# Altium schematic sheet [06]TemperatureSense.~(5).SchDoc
size A4; SheetNumber: 4; SheetTotal: 4
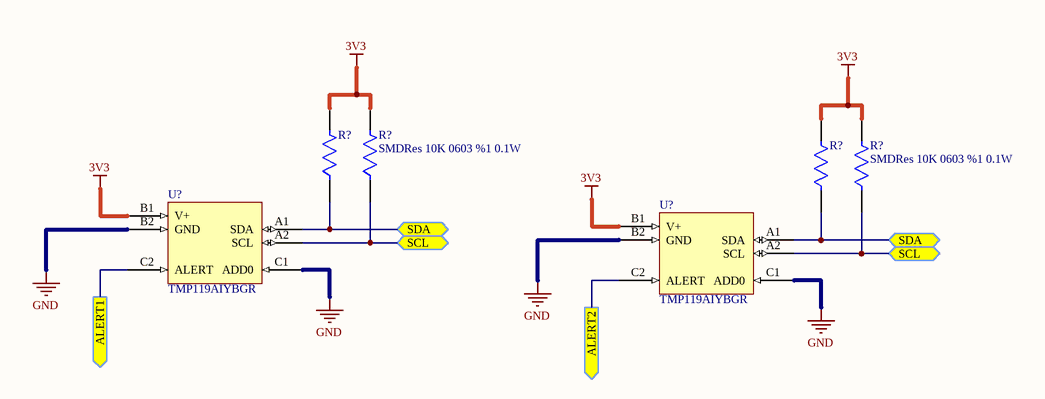
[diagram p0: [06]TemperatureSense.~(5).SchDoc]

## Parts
(Parts that share a designator on the sheet are numbered #1, #2 ... from top to bottom, then left to right.)
R?#1  SMDRes 10K 0603 %1 0.1W  [RESC1508X06N]  (value not drawn)
R?#2  SMDRes 10K 0603 %1 0.1W  [RESC1508X06N]
R?#3  SMDRes 10K 0603 %1 0.1W  [RESC1508X06N]  (value not drawn)
R?#4  SMDRes 10K 0603 %1 0.1W  [RESC1508X06N]
U?#1  TMP119AIYBGR  [BGA6C40P2X3_95X149X52]
U?#2  TMP119AIYBGR  [BGA6C40P2X3_95X149X52]

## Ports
ALERT1 (out), ALERT2 (out), SCL (bidir, see [05]BuckConverter[3D], [06]TemperatureSense[2C]), SCL (bidir, see [05]BuckConverter[3D], [06]TemperatureSense[4C]), SDA (bidir, see [05]BuckConverter[3D], [06]TemperatureSense[2B]), SDA (bidir, see [05]BuckConverter[3D], [06]TemperatureSense[4C])

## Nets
3V3: R?#1.2 R?#2.2 R?#3.2 R?#4.2 U?#1.B1(V+) U?#2.B1(V+)
GND: U?#1.B2(GND) U?#1.C1(ADD0) U?#2.B2(GND) U?#2.C1(ADD0)
ALERT1: U?#1.C2(ALERT) ; port ALERT1
ALERT2: U?#2.C2(ALERT) ; port ALERT2
SCL: R?#2.1 R?#4.1 U?#1.A2(SCL) U?#2.A2(SCL) ; port SCL
SDA: R?#1.1 R?#3.1 U?#1.A1(SDA) U?#2.A1(SDA) ; port SDA

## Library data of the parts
R?#1-R?#4 = CMP-00001-1-2: Res Thick Film 0603 10K Ohm 1% 0.1W(1/10W) ±100ppm/C Pad SMD T/R Automotive AEC-Q200; Manufacturer Number: RMCF0603FT10K0; Manufacturer: Stackpole Electronics Inc
U?#1 U?#2 = CMP-00021-1: Temperature Sensor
